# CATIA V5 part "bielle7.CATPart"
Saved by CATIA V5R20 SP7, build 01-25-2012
Part number: bielle7
Publications: "droite_bielle_7", "droite_pivot_7_5_6", "droite_pivot_7_0"
Bounding box of the stored display mesh (mm): x 0 to 0.5, y 0 to 2.08, z -1 to 1.17
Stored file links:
  U:\IAO\bielle7.CATPart
  U:\IAO\skl_brevet_iao.CATProduct
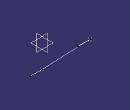
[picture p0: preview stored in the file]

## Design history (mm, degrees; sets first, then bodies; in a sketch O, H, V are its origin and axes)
Set1
  Point1 "point G": linked copy from another document
  Point2 "point H": linked copy from another document
Set2
  Line1 "droite_bielle_7": type PtPt, FirstPoint Point1, SecondPoint Point2
  Line2 "droite_pivot_7_5_6": type Normal, RefPoint Point1, RefSkin yz-plane, Start 0, End 0.5
  Line3 "droite_pivot_7_0": type Normal, RefPoint Point2, RefSkin yz-plane, Start 0, End 0.5
Body1 (main body)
